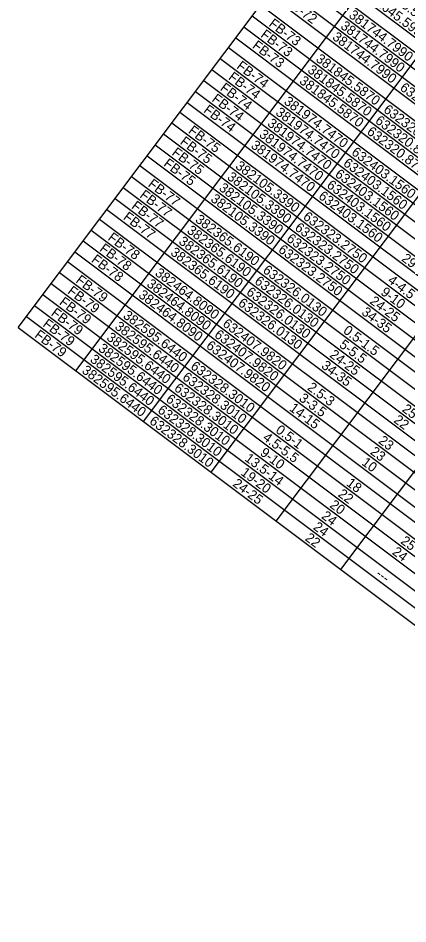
# Model space of a CAD drawing. Extents: x 627484.2 to 627514.4, y 367972.1 to 367996.9.
# Drawn here: x 627484.2 to 627486.41, y 367989.16 to 367994.31 of the extents above; entities that cross this region are included whole.
import ezdxf

# ---------------------------------------------------------------- set-up
doc = ezdxf.new("R2010")
doc.units = 0
doc.layers.add('Default', color=7, linetype='Continuous')

msp = doc.modelspace()

# ---------------------------------------------------------------- linework, layer by layer
at = {"layer": 'Default'}
for p, q in [((627485.9514, 367994.1999), (627487.7985, 367996.6597)), ((627486.3352, 367993.9116), (627488.1823, 367996.3715)), ((627485.805, 367994.6877), (627491.0444, 367990.7534)), ((627485.764, 367994.6332), (627491.0034, 367990.6988)), ((627485.7172, 367994.5708), (627490.9566, 367990.6365)), ((627484.2008, 367992.5515), (627485.6645, 367994.5006)), ((627485.6703, 367994.5084), (627490.9097, 367990.5741)), ((627485.6235, 367994.4461), (627490.8629, 367990.5117)), ((627485.5767, 367994.3837), (627490.8161, 367990.4494)), ((627485.5298, 367994.3213), (627490.7692, 367990.387)), ((627485.483, 367994.2589), (627490.7224, 367990.3246)), ((627484.5287, 367992.3053), (627485.9514, 367994.1999)), ((627485.4362, 367994.1966), (627490.6756, 367990.2622)), ((627485.3952, 367994.142), (627490.6346, 367990.2077)), ((627485.3483, 367994.0796), (627490.5877, 367990.1453)), ((627485.3015, 367994.0172), (627490.5409, 367990.0829)), ((627485.2547, 367993.9549), (627490.4941, 367990.0205)), ((627484.9125, 367992.0171), (627486.3352, 367993.9116)), ((627485.2078, 367993.8925), (627490.4472, 367989.9582)), ((627485.161, 367993.8301), (627490.4004, 367989.8958)), ((627485.12, 367993.7755), (627490.3594, 367989.8412)), ((627485.0732, 367993.7132), (627490.3126, 367989.7788)), ((627485.0263, 367993.6508), (627490.2657, 367989.7165)), ((627485.2964, 367991.7288), (627486.719, 367993.6234)), ((627484.9795, 367993.5884), (627490.2189, 367989.6541)), ((627484.9327, 367993.5261), (627490.1721, 367989.5917)), ((627484.8917, 367993.4715), (627490.1311, 367989.5372)), ((627484.8448, 367993.4091), (627490.0843, 367989.4748)), ((627484.798, 367993.3467), (627490.0374, 367989.4124)), ((627485.6667, 367991.4508), (627487.0894, 367993.3453)), ((627484.7512, 367993.2844), (627489.9906, 367989.35)), ((627484.7043, 367993.222), (627489.9437, 367989.2877)), ((627484.6634, 367993.1674), (627489.9028, 367989.2331)), ((627484.6165, 367993.105), (627489.8559, 367989.1707)), ((627486.0331, 367991.1756), (627487.4558, 367993.0702)), ((627484.5697, 367993.0427), (627489.8091, 367989.1083)), ((627484.5228, 367992.9803), (627489.7623, 367989.046)), ((627484.4819, 367992.9257), (627489.7213, 367988.9914)), ((627484.435, 367992.8633), (627489.6744, 367988.929)), ((627484.3882, 367992.801), (627489.6276, 367988.8666)), ((627484.3414, 367992.7386), (627489.5808, 367988.8043)), ((627484.2945, 367992.6762), (627489.5339, 367988.7419)), ((627484.2477, 367992.6139), (627489.4871, 367988.6795)), ((627484.2008, 367992.5515), (627489.4403, 367988.6172))]:
    msp.add_line(p, q, dxfattribs=at)

# ---------------------------------------------------------------- texts
for s, p in [('381645.5990', (627486.2559, 367994.5586)), ('381645.5990', (627486.2091, 367994.4962)), ('381645.5990', (627486.1622, 367994.4339)), ('FB-72', (627485.7127, 367994.3935)), ('381744.7990', (627486.0744, 367994.3169)), ('FB-73', (627485.6203, 367994.2677)), ('381744.7990', (627486.0276, 367994.2545)), ('FB-73', (627485.5735, 367994.2053)), ('FB-73', (627485.5267, 367994.143)), ('381744.7990', (627485.9807, 367994.1922)), ('381845.5870', (627485.8871, 367994.0674)), ('FB-74', (627485.4373, 367994.0272)), ('381845.5870', (627485.8402, 367994.005)), ('FB-74', (627485.3904, 367993.9648)), ('381845.5870', (627485.7934, 367993.9427)), ('FB-74', (627485.3436, 367993.9025)), ('632400.8520', (627486.3646, 367993.9039)), ('FB-74', (627485.2968, 367993.8401)), ('381974.7470', (627485.7056, 367993.8257)), ('FB-74', (627485.2499, 367993.7777)), ('381974.7470', (627485.6587, 367993.7634)), ('632320.8770', (627486.2709, 367993.7792)), ('381974.7470', (627485.6119, 367993.701)), ('632320.8770', (627486.2241, 367993.7168)), ('FB-75', (627485.1631, 367993.66)), ('381974.7470', (627485.5651, 367993.6386)), ('632320.8770', (627486.1772, 367993.6545)), ('FB-75', (627485.1163, 367993.5976)), ('FB-75', (627485.0694, 367993.5353)), ('381974.7470', (627485.5182, 367993.5762)), ('632403.1560', (627486.0894, 367993.5375)), ('FB-75', (627485.0226, 367993.4729)), ('632403.1560', (627486.0426, 367993.4751)), ('382105.3390', (627485.4304, 367993.4593)), ('382105.3390', (627485.3836, 367993.3969)), ('632403.1560', (627485.9957, 367993.4128)), ('FB-77', (627484.9341, 367993.3565)), ('382105.3390', (627485.3368, 367993.3345)), ('632403.1560', (627485.9489, 367993.3504)), ('FB-77', (627484.8873, 367993.2941)), ('382105.3390', (627485.2899, 367993.2722)), ('632403.1560', (627485.9021, 367993.288)), ('FB-77', (627484.8404, 367993.2317)), ('FB-77', (627484.7936, 367993.1693)), ('632323.2750', (627485.8143, 367993.1711)), ('382365.6190', (627485.2021, 367993.1552)), ('382365.6190', (627485.1553, 367993.0928)), ('632323.2750', (627485.7674, 367993.1087)), ('FB-78', (627484.7062, 367993.0521)), ('382365.6190', (627485.1084, 367993.0305)), ('632323.2750', (627485.7206, 367993.0463)), ('FB-78', (627484.6593, 367992.9897)), ('382365.6190', (627485.0616, 367992.9681)), ('632323.2750', (627485.6737, 367992.9839)), ('FB-78', (627484.6125, 367992.9273)), ('29-30', (627486.3739, 367992.9337)), ('632326.0130', (627485.5859, 367992.867)), ('FB-79', (627484.5242, 367992.8107)), ('382464.8090', (627484.9738, 367992.8512)), ('382464.8090', (627484.9269, 367992.7888)), ('632326.0130', (627485.5391, 367992.8046)), ('4-4.5', (627486.2952, 367992.8099)), ('FB-79', (627484.4774, 367992.7484)), ('382464.8090', (627484.8801, 367992.7264)), ('632326.0130', (627485.4923, 367992.7423)), ('9-10', (627486.2555, 367992.7422)), ('FB-79', (627484.4305, 367992.686)), ('632326.0130', (627485.4454, 367992.6799)), ('24-25', (627486.1934, 367992.6913)), ('FB-79', (627484.3837, 367992.6236)), ('382595.6440', (627484.7923, 367992.6095)), ('34-35', (627486.1466, 367992.6289)), ('FB-79', (627484.3369, 367992.5613)), ('632407.9820', (627485.3576, 367992.5629)), ('FB-79', (627484.29, 367992.4989)), ('382595.6440', (627484.7454, 367992.5471)), ('632407.9820', (627485.3108, 367992.5006)), ('0.5-1.5', (627486.0425, 367992.5241)), ('382595.6440', (627484.6986, 367992.4847)), ('5-5.5', (627486.0201, 367992.4435)), ('382595.6440', (627484.6518, 367992.4223)), ('632407.9820', (627485.2639, 367992.4382)), ('382595.6440', (627484.6049, 367992.36)), ('24-25', (627485.9651, 367992.3872)), ('382595.6440', (627484.5581, 367992.2976)), ('632328.3010', (627485.1761, 367992.3212)), ('34-35', (627485.9183, 367992.3248)), ('632328.3010', (627485.1293, 367992.2589)), ('632328.3010', (627485.0824, 367992.1965)), ('2.5-3', (627485.8391, 367992.2013)), ('3-3.5', (627485.7917, 367992.1394)), ('632328.3010', (627485.0356, 367992.1341)), ('632328.3010', (627484.9888, 367992.0717)), ('14-15', (627485.7368, 367992.0831)), ('25', (627486.3768, 367992.078)), ('632328.3010', (627484.9419, 367992.0094)), ('22', (627486.3292, 367992.0163)), ('0.5-1', (627485.6589, 367991.9587)), ('4.5-5.5', (627485.5859, 367991.916)), ('23', (627486.2427, 367991.8983)), ('9-10', (627485.5705, 367991.83)), ('23', (627486.1959, 367991.8359)), ('13.5-14', (627485.4831, 367991.7981)), ('10', (627486.1475, 367991.7747)), ('19-20', (627485.4606, 367991.7174)), ('24-25', (627485.4148, 367991.6543)), ('18', (627486.0604, 367991.6572)), ('22', (627486.013, 367991.5952)), ('20', (627485.966, 367991.533)), ('24', (627485.9191, 367991.4707)), ('24', (627485.8723, 367991.4083)), ('22', (627485.8257, 367991.3457)), ('25', (627486.3686, 367991.3283)), ('24', (627486.3207, 367991.2667)), ('---', (627486.2272, 367991.1418))]:
    msp.add_text(s, height=0.055, rotation=323.0968, dxfattribs=at).set_placement(p)

doc.saveas('drawing.dxf')
